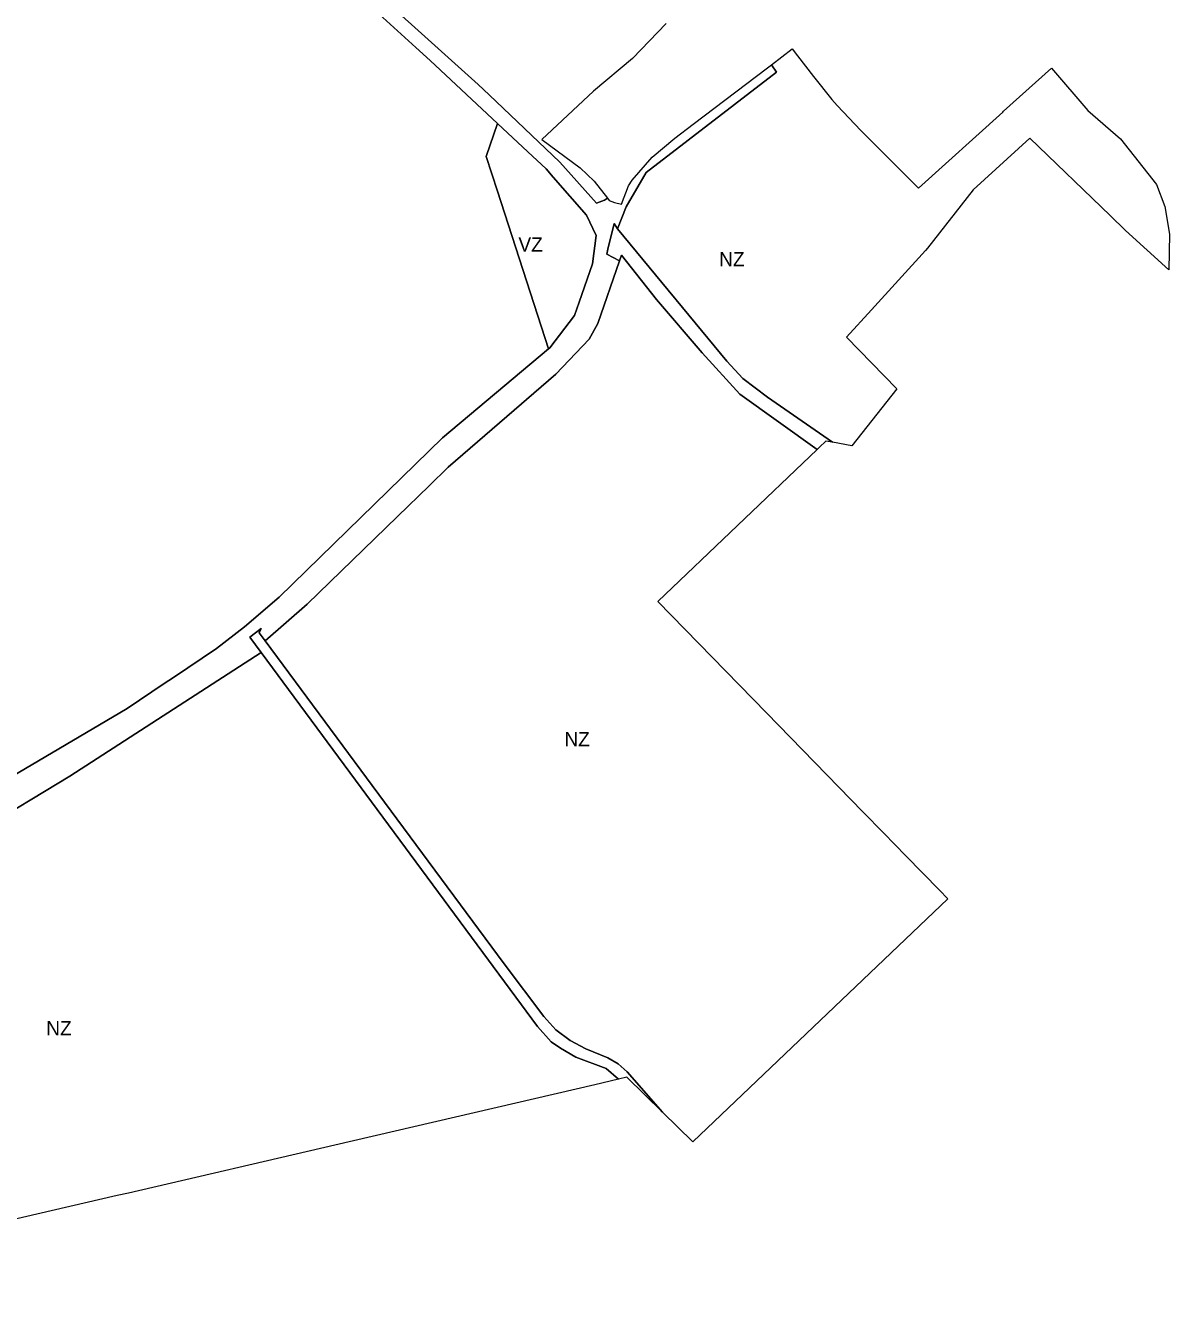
# Model space of a CAD drawing. Extents: x -650451 to -642268, y -1075216 to -1066610.
# Drawn here: x -644450 to -643489, y -1073553 to -1072479 of the extents above; entities that cross this region are included whole.
import ezdxf

# ---------------------------------------------------------------- set-up
doc = ezdxf.new("R2010")
doc.units = 0
doc.header["$LTSCALE"] = 4.8
for name, color, linetype, lineweight in [('15', 7, 'Continuous', 13), ('24', 7, 'Continuous', 13), ('36', 7, 'Continuous', 13), ('46', 7, 'Continuous', 13)]:
    doc.layers.add(name, color=color, linetype=linetype, lineweight=lineweight)
doc.layers.add('62', color=7, linetype='Continuous')

msp = doc.modelspace()

# ---------------------------------------------------------------- linework, layer by layer
at = {"layer": '15'}
for points in [[(-643950.72, -1072677.23), (-643961.44, -1072671.57), (-643960.39, -1072667.32), (-643955.1, -1072645.88), (-643952.38, -1072650.16)], [(-643952.38, -1072650.16), (-643860.56, -1072761.63), (-643847.1, -1072776.06), (-643826.25, -1072791.8), (-643771.73, -1072829.64)], [(-643784.73, -1072835.75), (-643849.5, -1072789.12), (-643881.34, -1072754.6), (-643919.55, -1072709.6), (-643949.07, -1072672.43), (-643950.72, -1072677.23)], [(-643771.73, -1072829.64), (-643777.25, -1072828.61), (-643782.64, -1072833.75), (-643784.73, -1072835.75)], [(-644251.67, -1073006.23), (-644261.15, -1072993.37), (-644251.63, -1072986.07), (-644253.34, -1072989.81), (-644248.39, -1072996.52)], [(-644248.39, -1072996.52), (-644148.02, -1073132.2), (-644047.66, -1073267.87), (-644014.28, -1073312.31), (-644004.23, -1073323.44), (-643992.28, -1073332.5), (-643979.05, -1073339.57), (-643960.48, -1073347.01), (-643951.85, -1073352.05), (-643944.35, -1073358.67), (-643914.7, -1073392.62)], [(-643951.41, -1073364.95), (-643962.02, -1073356.06), (-643987.35, -1073346.4), (-644000.4, -1073338.94), (-644007.99, -1073333.47), (-644019.54, -1073320.72), (-644042.52, -1073289.59), (-644251.67, -1073006.23)], [(-643914.7, -1073392.62), (-643944.57, -1073363.36), (-643951.41, -1073364.95)]]:
    msp.add_lwpolyline(points, dxfattribs=at)
at = {"layer": '24'}
for points in [[(-645054.89, -1071761.24), (-645032.12, -1071770.35), (-645018.25, -1071775.91), (-644960.64, -1071817.09), (-644949.54, -1071825.04), (-644862.66, -1071887.21), (-644695.23, -1072018.87), (-644636.46, -1072065.09), (-644588.85, -1072102.53), (-644478.48, -1072182.31), (-644419.24, -1072221.55), (-644364.37, -1072263.96), (-644360.49, -1072267.17), (-644321.52, -1072299.46), (-644287.37, -1072330.05), (-644186.79, -1072422.99), (-644069.52, -1072528.88), (-644060.18, -1072537.75), (-644000.81, -1072594.17), (-643970.07, -1072628.8), (-643963.42, -1072626.24), (-643960.87, -1072624.65)], [(-644053.21, -1072561.84), (-644109.86, -1072508.89), (-644121.7, -1072497.82), (-644272.87, -1072360.39), (-644289.42, -1072345.33), (-644303.63, -1072333.96), (-644431.08, -1072231.95), (-644480.98, -1072196.8), (-644487.07, -1072191.01), (-644595.43, -1072112.45), (-644704.85, -1072026.63), (-644782.12, -1071966.02), (-644848.51, -1071913.94), (-644850.99, -1071912), (-644871.18, -1071896.16), (-644923.07, -1071858.92), (-644965.77, -1071828.29), (-644996.62, -1071808.6), (-644999.75, -1071806.6), (-645006.76, -1071802.39), (-645021.3, -1071791.05)], [(-643960.87, -1072624.65), (-643959.4, -1072626.57), (-643954.77, -1072628.14), (-643948.93, -1072629.7), (-643943.11, -1072614.26), (-643940.03, -1072609.4), (-643923.21, -1072590.2), (-643904.32, -1072574.09), (-643888.68, -1072562.22), (-643826.36, -1072514.9), (-643823.09, -1072512.42)], [(-643823.09, -1072512.42), (-643818.72, -1072518.56), (-643928.21, -1072602.89), (-643944.98, -1072631.75), (-643952.38, -1072650.16)], [(-644010.26, -1072751.03), (-644009.27, -1072750.21), (-643988.48, -1072723.23), (-643984.55, -1072711.81), (-643973.49, -1072679.63), (-643970.28, -1072655.79), (-643978.55, -1072638.72), (-644006.41, -1072606.81), (-644012.35, -1072600), (-644020.16, -1072592.7), (-644023.62, -1072589.48), (-644053.21, -1072561.84)], [(-643952.38, -1072650.16), (-643955.1, -1072645.88), (-643960.39, -1072667.32), (-643961.44, -1072671.57), (-643950.72, -1072677.23)], [(-643950.72, -1072677.23), (-643968.86, -1072729.95), (-643976.09, -1072743.13), (-644004.24, -1072772.48), (-644057.56, -1072818.67), (-644094.57, -1072850.72), (-644110.69, -1072866.34), (-644137.11, -1072891.95), (-644213.19, -1072965.71), (-644248.39, -1072996.52)], [(-644529.95, -1073158.06), (-644486.21, -1073126.35), (-644473.14, -1073117.58), (-644364.45, -1073053.47), (-644333.31, -1073032.51), (-644325.45, -1073027.23), (-644289.29, -1073002.89), (-644265.63, -1072984.81), (-644236.74, -1072959.83), (-644099.4, -1072825.88), (-644010.26, -1072751.03)], [(-644248.39, -1072996.52), (-644253.34, -1072989.81), (-644251.63, -1072986.07), (-644261.15, -1072993.37), (-644251.67, -1073006.23)], [(-644251.67, -1073006.23), (-644412.36, -1073110.27), (-644488.53, -1073156.12), (-644510.49, -1073173.7), (-644547.27, -1073203.12), (-644577.34, -1073226.12), (-644678.02, -1073303.11), (-644698.13, -1073318.48), (-644776.32, -1073383.08), (-644795.99, -1073395.08), (-644796.12, -1073395.56), (-644795.76, -1073403.59), (-644797.05, -1073407.39), (-644799.16, -1073413.58), (-644801.88, -1073417.95), (-644796.05, -1073442.48), (-644782.57, -1073482.57), (-644764.68, -1073545.3), (-644762.37, -1073553.42)]]:
    msp.add_lwpolyline(points, dxfattribs=at)
at = {"layer": '36'}
for points in [[(-644010.26, -1072751.03), (-644053.2, -1072618.77), (-644062.69, -1072589.53), (-644053.21, -1072561.84)], [(-644053.21, -1072561.84), (-644023.62, -1072589.48), (-644020.16, -1072592.7), (-644012.35, -1072600), (-644006.41, -1072606.81), (-643978.55, -1072638.72), (-643970.28, -1072655.79), (-643973.49, -1072679.63), (-643984.55, -1072711.81), (-643988.48, -1072723.23), (-644009.27, -1072750.21), (-644010.26, -1072751.03)]]:
    msp.add_lwpolyline(points, dxfattribs=at)
at = {"layer": '46'}
for points in [[(-643960.87, -1072624.65), (-643963.42, -1072626.24), (-643970.07, -1072628.8), (-644000.81, -1072594.17), (-644060.18, -1072537.75), (-644069.52, -1072528.88), (-644186.79, -1072422.99), (-644287.37, -1072330.05), (-644321.52, -1072299.46), (-644360.49, -1072267.17), (-644364.37, -1072263.96), (-644419.24, -1072221.55), (-644478.48, -1072182.31), (-644588.85, -1072102.53), (-644636.46, -1072065.09), (-644695.23, -1072018.87), (-644862.66, -1071887.21), (-644949.54, -1071825.04), (-644960.64, -1071817.09), (-645018.25, -1071775.91), (-645032.12, -1071770.35), (-645054.89, -1071761.24)], [(-645021.3, -1071791.05), (-645006.76, -1071802.39), (-644999.75, -1071806.6), (-644996.62, -1071808.6), (-644965.77, -1071828.29), (-644923.07, -1071858.92), (-644871.18, -1071896.16), (-644850.99, -1071912), (-644848.51, -1071913.94), (-644782.12, -1071966.02), (-644704.85, -1072026.63), (-644595.43, -1072112.45), (-644487.07, -1072191.01), (-644480.98, -1072196.8), (-644431.08, -1072231.95), (-644303.63, -1072333.96), (-644289.42, -1072345.33), (-644272.87, -1072360.39), (-644121.7, -1072497.82), (-644109.86, -1072508.89), (-644053.21, -1072561.84)], [(-643911.4, -1072477.79), (-643939.76, -1072507.17), (-643972.47, -1072534.49), (-644015.96, -1072575.24), (-643983.64, -1072599.15), (-643971.94, -1072610.28), (-643960.87, -1072624.65)], [(-643823.09, -1072512.42), (-643805.58, -1072499.12), (-643801.18, -1072505.04), (-643787.69, -1072522.22), (-643772.38, -1072541.7), (-643767.84, -1072546.53), (-643748, -1072567.6), (-643746.13, -1072569.58), (-643699.45, -1072616.14), (-643628.66, -1072552.16), (-643627.98, -1072551.54), (-643587.82, -1072515.24), (-643557.17, -1072550.96), (-643529.75, -1072574.65), (-643499.6, -1072613.11), (-643492.55, -1072631.48), (-643488.71, -1072654.91), (-643489.15, -1072684.88), (-643525.62, -1072651.6), (-643538.58, -1072639.1), (-643606.02, -1072574.01), (-643653.54, -1072617.62), (-643691.94, -1072666.45), (-643693.54, -1072668.49), (-643738.9, -1072718.28), (-643759.87, -1072741.29), (-643717.83, -1072784.76), (-643755.57, -1072832.64), (-643771.73, -1072829.64)], [(-643952.38, -1072650.16), (-643944.98, -1072631.75), (-643928.21, -1072602.89), (-643818.72, -1072518.56), (-643823.09, -1072512.42)], [(-644053.21, -1072561.84), (-644062.69, -1072589.53), (-644053.2, -1072618.77), (-644010.26, -1072751.03)], [(-643771.73, -1072829.64), (-643826.25, -1072791.8), (-643847.1, -1072776.06), (-643860.56, -1072761.63), (-643952.38, -1072650.16)], [(-644248.39, -1072996.52), (-644213.19, -1072965.71), (-644137.11, -1072891.95), (-644110.69, -1072866.34), (-644094.57, -1072850.72), (-644057.56, -1072818.67), (-644004.24, -1072772.48), (-643976.09, -1072743.13), (-643968.86, -1072729.95), (-643950.72, -1072677.23)], [(-643950.72, -1072677.23), (-643949.07, -1072672.43), (-643919.55, -1072709.6), (-643881.34, -1072754.6), (-643849.5, -1072789.12), (-643784.73, -1072835.75)], [(-644010.26, -1072751.03), (-644099.4, -1072825.88), (-644236.74, -1072959.83), (-644265.63, -1072984.81), (-644289.29, -1073002.89), (-644325.45, -1073027.23), (-644333.31, -1073032.51), (-644364.45, -1073053.47), (-644473.14, -1073117.58), (-644486.21, -1073126.35), (-644529.95, -1073158.06)], [(-643784.73, -1072835.75), (-643918.49, -1072963.57), (-643827.17, -1073057.19), (-643746.24, -1073140.18), (-643728.75, -1073158.08), (-643710.23, -1073177.1), (-643682, -1073206.04), (-643674.98, -1073213.24), (-643888.98, -1073417.72), (-643914.7, -1073392.62)], [(-643914.7, -1073392.62), (-643944.35, -1073358.67), (-643951.85, -1073352.05), (-643960.48, -1073347.01), (-643979.05, -1073339.57), (-643992.28, -1073332.5), (-644004.23, -1073323.44), (-644014.28, -1073312.31), (-644047.66, -1073267.87), (-644148.02, -1073132.2), (-644248.39, -1072996.52)], [(-644762.37, -1073553.42), (-644764.68, -1073545.3), (-644782.57, -1073482.57), (-644796.05, -1073442.48), (-644801.88, -1073417.95), (-644799.16, -1073413.58), (-644797.05, -1073407.39), (-644795.76, -1073403.59), (-644796.12, -1073395.56), (-644795.99, -1073395.08), (-644776.32, -1073383.08), (-644698.13, -1073318.48), (-644678.02, -1073303.11), (-644577.34, -1073226.12), (-644547.27, -1073203.12), (-644510.49, -1073173.7), (-644488.53, -1073156.12), (-644412.36, -1073110.27), (-644251.67, -1073006.23)], [(-644251.67, -1073006.23), (-644042.52, -1073289.59), (-644019.54, -1073320.72), (-644007.99, -1073333.47), (-644000.4, -1073338.94), (-643987.35, -1073346.4), (-643962.02, -1073356.06), (-643951.41, -1073364.95)], [(-643951.41, -1073364.95), (-643971.48, -1073369.61), (-644189.82, -1073420.36), (-644363.26, -1073460.66), (-644372.58, -1073462.83), (-644452.17, -1073481.3), (-644762.37, -1073553.42)]]:
    msp.add_lwpolyline(points, dxfattribs=at)

# ---------------------------------------------------------------- texts
at = {"layer": '62'}
for s, p in [('VZ', (-644035.614, -1072669.477)), ('NZ', (-643867.015, -1072681.762)), ('NZ', (-643996.99, -1073085.147)), ('NZ', (-644432.298, -1073328.137))]:
    msp.add_text(s, height=12, dxfattribs=at).set_placement(p)

doc.saveas('drawing.dxf')
